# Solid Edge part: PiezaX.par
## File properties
Author: ADI
Template: Normal.par
Last saved by: ADI
Revision: 3
Application: Solid Edge
Densidad: 0 kg/mm^3
Precisión: 0,99
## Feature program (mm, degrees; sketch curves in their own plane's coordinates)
sketch for "unnamed Protrusion 1" plane through (0, 0, 0) normal (0, 0, 1) x-axis (1, 0, 0)
  line (-23.068, 0) -> (102.932, 0)
  line (102.932, 0) -> (102.932, 75)
  line (102.932, 75) -> (-23.068, 75)
  line (-23.068, 75) -> (-23.068, 0)
extrude "unnamed Protrusion 1" add finite 3 along +normal
sketch for "VaciadoExtruido_3" plane through (39.932, 37.5, 3) normal (0, 0, 1) x-axis (0, 1, 0)
  line (-23.5, 63) -> (30.5, 63)
  line (30.5, 63) -> (30.5, 60)
  line (30.5, 60) -> (-23.5, 60)
  line (-23.5, 60) -> (-23.5, 63)
extrude "VaciadoExtruido_3" cut finite 3 along -normal
sketch for "VaciadoExtruido_4" plane through (158.5575, 41.3912, 3) normal (0, 0, 1) x-axis (0, 1, 0)
  line (26.6088, 55.6255) -> (-27.3912, 55.6255)
  line (-27.3912, 55.6255) -> (-27.3912, 58.6255)
  line (-27.3912, 58.6255) -> (26.6088, 58.6255)
  line (26.6088, 58.6255) -> (26.6088, 55.6255)
extrude "VaciadoExtruido_4" cut finite 3 along -normal
sketch for "VaciadoExtruido_5" plane through (39.932, 37.5, 3) normal (0, 0, 1) x-axis (0, 1, 0)
  line (-30.5, 63) -> (-37.5, 63)
  line (-37.5, 63) -> (-37.5, 60)
  line (-37.5, 60) -> (-30.5, 60)
  line (-30.5, 60) -> (-30.5, 63)
extrude "VaciadoExtruido_5" cut finite 3 along -normal
sketch for "VaciadoExtruido_6" plane through (39.932, 37.5, 3) normal (0, 0, 1) x-axis (0, 1, 0)
  line (-37.5, -63) -> (-30.5, -63)
  line (-30.5, -63) -> (-30.5, -60)
  line (-30.5, -60) -> (-37.5, -60)
  line (-37.5, -60) -> (-37.5, -63)
extrude "VaciadoExtruido_6" cut finite 3 along -normal
sketch for "VaciadoExtruido_7" plane through (39.932, 37.5, 3) normal (0, 0, 1) x-axis (0, 1, 0)
  line (22.5, 60) -> (22.5, 33.0711)
  arc centre (17.5, 33.0711) radius 5 from (22.5, 33.0711) to (13.9645, 29.5355) cw
  line (13.9645, 29.5355) -> (-16.5, 60)
  line (-16.5, 60) -> (22.5, 60)
  dimension (linear) = 16.5
extrude "VaciadoExtruido_7" cut finite 3 along -normal
sketch for "VaciadoExtruido_8" plane through (39.932, 37.5, 3) normal (0, 0, 1) x-axis (0, 1, 0)
  line (22.5, -60) -> (22.5, -34.4218)
  arc centre (16.9405, -34.4218) radius 5.5595 from (22.5, -34.4218) to (13.0093, -30.4907) ccw
  line (13.0093, -30.4907) -> (-16.5, -60)
  line (-16.5, -60) -> (22.5, -60)
extrude "VaciadoExtruido_8" cut finite 3 along -normal
sketch for "VaciadoExtruido_9" plane through (39.932, 37.5, 3) normal (0, 0, 1) x-axis (0.707107, -0.707107, 0)
  line (-15.9099, -68.9429) -> (-15.9099, 6.4538)
  arc centre (-6.4538, 6.4538) radius 9.4561 from (-15.9099, 6.4538) to (-6.4538, 15.9099) cw
  line (-6.4538, 15.9099) -> (68.9429, 15.9099)
  line (68.9429, 15.9099) -> (-15.9099, -68.9429)
extrude "VaciadoExtruido_9" cut finite 3 along -normal
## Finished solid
Body 1: solid body, 28 faces, 78 edges, 52 vertices.
  Faces by surface: plane 25, cylinder 3
  Edges by curve: line 72, circle 6
Bounding box of the edges (mm): 126.000 x 75.000 x 3.000, from (-23.068, 0, 0) to (102.932, 75, 3).
Cylindrical faces by radius (mm): R5 x1, R5.5595 x1, R9.4561 x1
Planar faces by outward normal: +x 5, +y 3, +z 1, -x 5, -y 6, -z 1, oblique 4
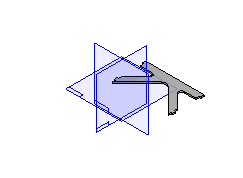
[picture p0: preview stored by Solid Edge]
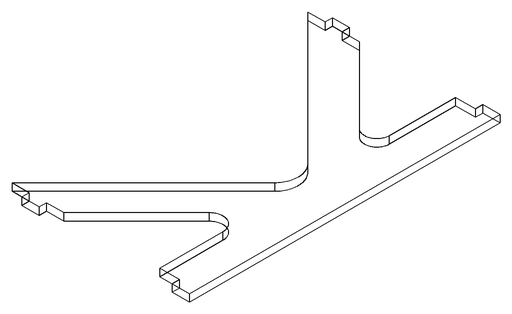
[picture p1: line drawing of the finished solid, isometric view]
